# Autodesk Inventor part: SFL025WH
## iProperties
Created: 2005-10
Part Number: SFL025WH
Material: 1.4301 X5CrNi10-10 A2
Document SubType Name: Modellieren
Designer: Mittelmeyer
Manufacturer: Standard
Standards Organization: Custom
Description: Drehdurchführung mit Flansch d=25mm
Author: Mittelmeyer
Comments: Ferrofluidics
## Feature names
1. Extrusion2
2. Extrusion3
3. Extrusion4
4. Extrusion5
5. Extrusion6
6. Rundung3 [Fillet]
7. Fase1 [Chamfer]
8. Fase2 [Chamfer]
9. Bohrung1 [Hole]
10. Runde Anordnung1 [Circular Pattern]
11. Bohrung2 [Hole]
